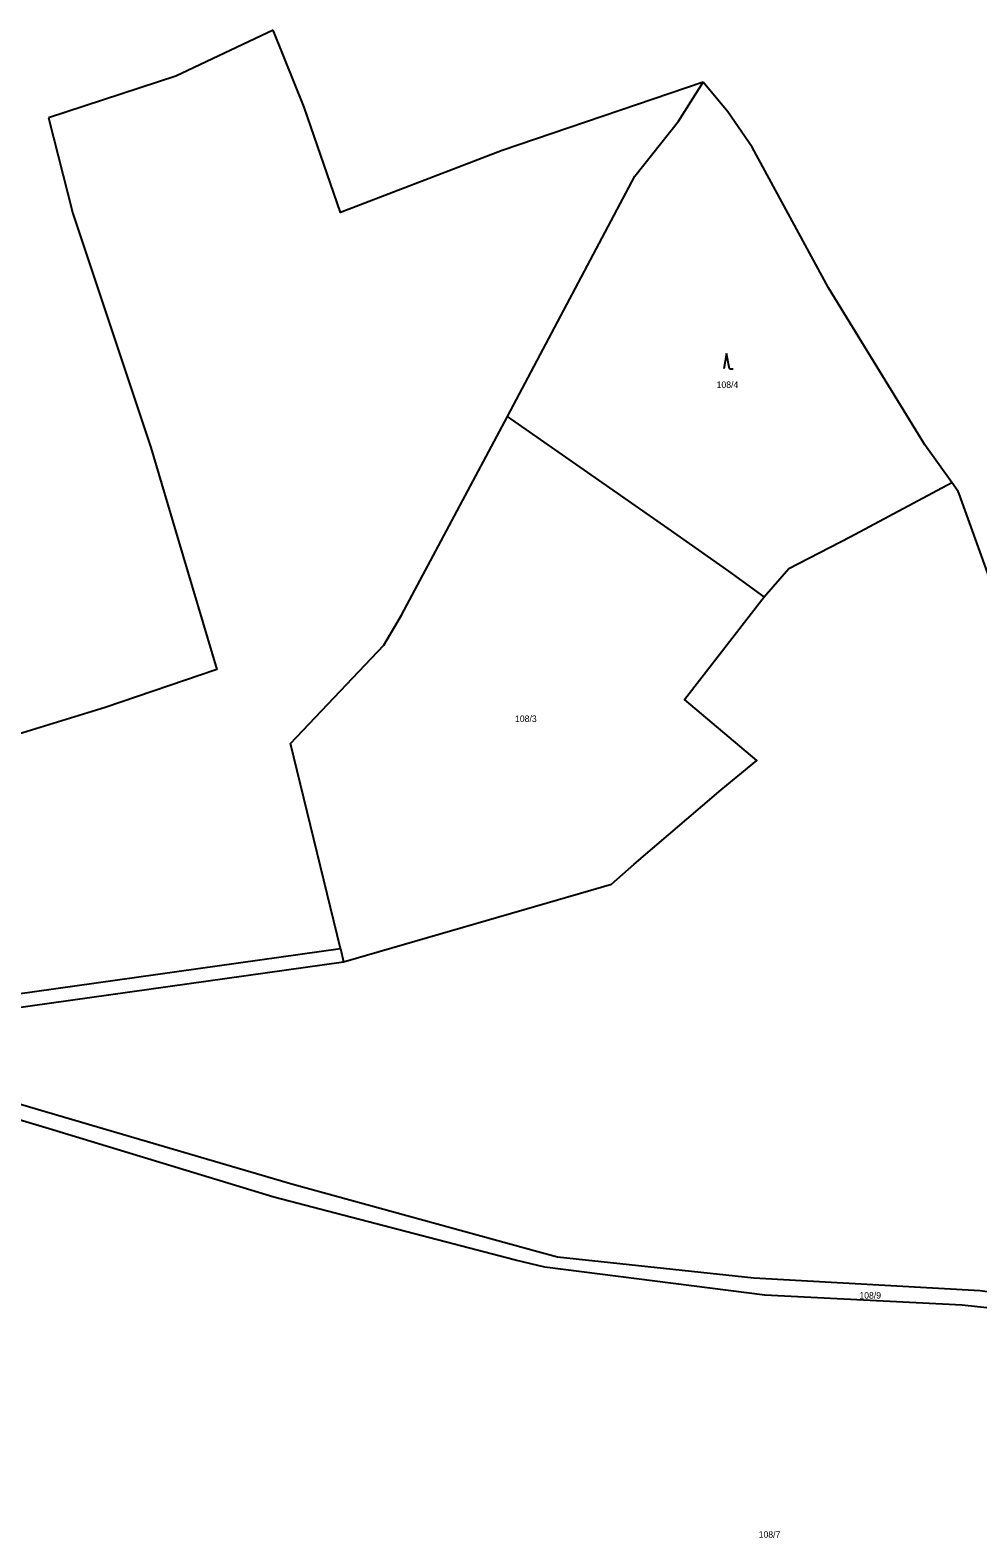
# Model space of a CAD drawing. Extents: x -779723 to -777378, y -1011169 to -1009297.
# Drawn here: x -778429.6 to -778181.3, y -1010169.5 to -1009774.5 of the extents above; entities that cross this region are included whole.
import ezdxf

# ---------------------------------------------------------------- set-up
doc = ezdxf.new("R2010")
doc.units = 0
for name, color, linetype in [('Hranice parcel', 7, 'Continuous'), ('Parcelní čísla', 7, 'Continuous'), ('Značky kultur', 7, 'Continuous')]:
    doc.layers.add(name, color=color, linetype=linetype)

msp = doc.modelspace()

# ---------------------------------------------------------------- linework, layer by layer
at = {"layer": 'Hranice parcel'}
for p, q in [((-778357.79, -1009794.65), (-778365.92, -1009774.47)), ((-778188.09, -1009893.03), (-778195.2, -1009883.12)), ((-778176.01, -1009924.09), (-778186.19, -1009895.98)), ((-778348.28, -1010015.11), (-778347.45, -1010018.54))]:
    msp.add_line(p, q, dxfattribs=at)
for points in [[(-778365.92, -1009774.47), (-778391.39, -1009786.56), (-778424.79, -1009797.42)], [(-778253.23, -1009788.09), (-778305.88, -1009806.04), (-778348.3, -1009822.26), (-778357.79, -1009794.65)], [(-778304.51, -1009875.73), (-778271.19, -1009812.73), (-778259.7, -1009798.31), (-778253.23, -1009788.09)], [(-778240.42, -1009805.17), (-778246.76, -1009795.86), (-778253.23, -1009788.09)], [(-778424.79, -1009797.42), (-778418.38, -1009822.49), (-778397.98, -1009883.84), (-778390.73, -1009908.28), (-778380.68, -1009942.03), (-778409.93, -1009951.93), (-778441.85, -1009961.74), (-778452.32, -1009927.34), (-778461.29, -1009896.85), (-778477.95, -1009840.27)], [(-778195.2, -1009883.12), (-778220.4, -1009842.01), (-778240.42, -1009805.17)], [(-778348.28, -1010015.11), (-778361.41, -1009961.37), (-778336.92, -1009935.65), (-778332.32, -1009927.75), (-778304.51, -1009875.73)], [(-778237.26, -1009922.95), (-778246.53, -1009916.19), (-778262.42, -1009905), (-778304.51, -1009875.73)], [(-778237.26, -1009922.95), (-778230.81, -1009915.54), (-778214.71, -1009907.2), (-778188.09, -1009893.03)], [(-778186.19, -1009895.98), (-778186.4, -1009895.39), (-778188.09, -1009893.03)], [(-778347.45, -1010018.54), (-778294.15, -1010003.11), (-778277.25, -1009998.22), (-778271.29, -1009993.02), (-778248.57, -1009973.51), (-778239.17, -1009965.87), (-778258.11, -1009949.88), (-778237.26, -1009922.95)], [(-778541.4, -1010042.99), (-778520.25, -1010039.26), (-778497.51, -1010036.07), (-778348.28, -1010015.11)], [(-778507.76, -1010041.04), (-778479.97, -1010037.14), (-778465.13, -1010035.06), (-778347.45, -1010018.54)], [(-777915.32, -1010130.76), (-777965.67, -1010115.09), (-777984.81, -1010115.73), (-777999.17, -1010116.04), (-778039.22, -1010109.98), (-778074.01, -1010110.38), (-778103.23, -1010113.41), (-778121.64, -1010116.47), (-778151.12, -1010114.44), (-778174.14, -1010109.8), (-778185.39, -1010108.53), (-778237.09, -1010105.96), (-778294.76, -1010098.57), (-778302.43, -1010096.77), (-778365.7, -1010080.27), (-778423.7, -1010062.57), (-778466.13, -1010049.97), (-778520.34, -1010042.8)], [(-778507.76, -1010041.04), (-778463.16, -1010047.36), (-778448.54, -1010051.05), (-778413.41, -1010061.34), (-778360.73, -1010076.84), (-778296.58, -1010094.47), (-778291.4, -1010095.84), (-778239.95, -1010101.4), (-778180.65, -1010104.69), (-778145.9, -1010109.73), (-778118.76, -1010110.86), (-778075.46, -1010104.51), (-778036.74, -1010105.05), (-778006.46, -1010110.09), (-777991.99, -1010110.55), (-777964.85, -1010110.4), (-777924.86, -1010123.86)]]:
    msp.add_lwpolyline(points, dxfattribs=at)
at = {"layer": 'Značky kultur'}
for p, q in [((-778247.11, -1009859.2), (-778247.86, -1009863.2)), ((-778246.36, -1009863.2), (-778247.11, -1009859.2)), ((-778246.36, -1009863.2), (-778245.36, -1009863.2))]:
    msp.add_line(p, q, dxfattribs=at)

# ---------------------------------------------------------------- texts
at = {"layer": 'Parcelní čísla'}
for s, p in [('108/4', (-778249.73, -1009868.22)), ('108/3', (-778302.55, -1009955.74)), ('108/9', (-778212.32, -1010106.83)), ('108/7', (-778238.7, -1010169.48))]:
    msp.add_text(s, height=1.7, dxfattribs=at).set_placement(p)

doc.saveas('drawing.dxf')
